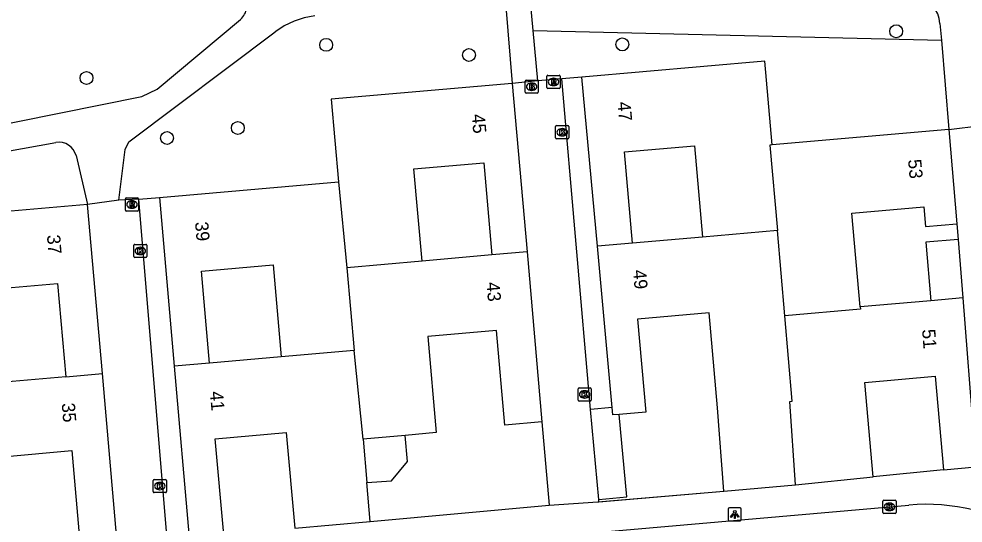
# Model space of a CAD drawing. Extents: x 162990 to 165007, y 383433 to 384336.
# Drawn here: x 164183.1 to 164254.8, y 383936.3 to 383974.6 of the extents above; entities that cross this region are included whole.
import ezdxf

# ---------------------------------------------------------------- set-up
doc = ezdxf.new("R2010")
doc.units = 0
for name, color, linetype in [('IMGEO_Boom', 7, 'Continuous'), ('IMGEO_Brandkraan', 7, 'Continuous'), ('IMGEO_Groenvoorziening', 7, 'Continuous'), ('IMGEO_Kolk', 7, 'Continuous'), ('IMGEO_Lichtpunt', 7, 'Continuous'), ('IMGEO_Muur', 7, 'Continuous'), ('IMGEO_Pand', 7, 'Continuous'), ('IMGEO_Pand_nummerreeks', 7, 'Continuous'), ('IMGEO_Rijbaan_lokaal_open', 7, 'Continuous'), ('IMGEO_Rioolput', 7, 'Continuous'), ('IMGEO_Voetpad_halfverhard', 7, 'Continuous'), ('IMGEO_Voetpad_open', 7, 'Continuous')]:
    doc.layers.add(name, color=color, linetype=linetype)

msp = doc.modelspace()

# ---------------------------------------------------------------- linework, layer by layer
at = {"layer": 'IMGEO_Boom'}
for centre in [(164249.696, 383973.69), (164206.398, 383972.653), (164228.892, 383972.688), (164217.243, 383971.88), (164188.193, 383970.138), (164199.688, 383966.337), (164194.307, 383965.574)]:
    msp.add_circle(centre, 0.489, dxfattribs=at)
at = {"layer": 'IMGEO_Brandkraan'}
for p, q in [((164221.505, 383969.049), (164221.505, 383969.901)), ((164221.58, 383969.975), (164222.432, 383969.975)), ((164221.993, 383969.755), (164222.018, 383969.755)), ((164222.506, 383969.901), (164222.506, 383969.049)), ((164222.432, 383968.975), (164221.58, 383968.975)), ((164222.016, 383969.195), (164221.991, 383969.195))]:
    msp.add_line(p, q, dxfattribs=at)
for points in [[(164221.505, 383969.049), (164221.505, 383969.901)], [(164221.58, 383969.975), (164222.432, 383969.975)], [(164221.853, 383969.675), (164221.853, 383969.275), (164222.066, 383969.275)], [(164222.084, 383969.675), (164221.853, 383969.675)], [(164222.032, 383969.594), (164221.978, 383969.594), (164221.978, 383969.518)], [(164221.978, 383969.518), (164222.031, 383969.518)], [(164222.04, 383969.442), (164221.978, 383969.442), (164221.978, 383969.361)], [(164221.978, 383969.361), (164222.04, 383969.361)], [(164222.506, 383969.901), (164222.506, 383969.049)], [(164222.432, 383968.975), (164221.58, 383968.975)]]:
    msp.add_lwpolyline(points, dxfattribs=at)
for centre, radius, start, end in [((164221.582, 383969.899), 0.0765, 91.55205, 178.44795), ((164221.582, 383969.899), 0.0765, 91.55205, 178.44795), ((164222.033, 383969.556), 0.0379, 267.82845, 90.93552), ((164222.041, 383969.401), 0.0404, 269.87594, 90.50774), ((164222.072, 383969.526), 0.251, 268.66757, 293.53466), ((164222.088, 383969.53), 0.145, 59.4692, 91.53667), ((164222.113, 383969.577), 0.0922, 285.51372, 58.15012), ((164222.118, 383969.385), 0.105, 301.31148, 78.98903), ((164222.43, 383969.899), 0.0765, 1.55205, 88.44795), ((164222.43, 383969.899), 0.0765, 1.55205, 88.44795), ((164221.582, 383969.051), 0.0765, 181.55205, 268.44795), ((164221.582, 383969.051), 0.0765, 181.55205, 268.44795), ((164222.43, 383969.051), 0.0765, 271.55205, 358.44795), ((164222.43, 383969.051), 0.0765, 271.55205, 358.44795)]:
    msp.add_arc(centre, radius, start, end, dxfattribs=at)
for centre, major_axis, ratio, start_param, end_param in [((164221.992, 383969.475), (-0.387, 0.002), 0.722429, 4.712389, 7.853982), ((164222.017, 383969.475), (-0.39, 0.002), 0.717154, 1.570796, 4.712389)]:
    msp.add_ellipse(centre, major_axis=major_axis, ratio=ratio, start_param=start_param, end_param=end_param, dxfattribs=at)
at = {"layer": 'IMGEO_Groenvoorziening'}
for points in [[(164222.131, 383973.745), (164253.129, 383973.007)], [(164225.812, 383970.195), (164224.31, 383970.064)], [(164192.16, 383960.917), (164193.738, 383961.045)]]:
    msp.add_lwpolyline(points, dxfattribs=at)
at = {"layer": 'IMGEO_Kolk'}
for p, q in [((164223.829, 383965.588), (164223.829, 383966.44)), ((164223.904, 383966.514), (164224.756, 383966.514)), ((164224.83, 383966.44), (164224.83, 383965.588)), ((164224.34, 383965.734), (164224.315, 383965.734)), ((164224.317, 383966.294), (164224.342, 383966.294)), ((164224.756, 383965.514), (164223.904, 383965.514)), ((164191.78, 383956.567), (164191.78, 383957.419)), ((164191.855, 383957.493), (164192.707, 383957.493)), ((164192.268, 383957.273), (164192.293, 383957.273)), ((164192.781, 383957.419), (164192.781, 383956.567)), ((164192.707, 383956.493), (164191.855, 383956.493)), ((164192.291, 383956.713), (164192.266, 383956.713)), ((164225.531, 383945.66), (164225.531, 383946.512)), ((164225.606, 383946.586), (164226.458, 383946.586)), ((164226.019, 383946.366), (164226.044, 383946.366)), ((164226.532, 383946.512), (164226.532, 383945.66)), ((164226.042, 383945.806), (164226.017, 383945.806)), ((164226.458, 383945.586), (164225.606, 383945.586)), ((164193.264, 383938.696), (164193.264, 383939.548)), ((164193.339, 383939.622), (164194.191, 383939.622)), ((164193.752, 383939.402), (164193.777, 383939.402)), ((164194.265, 383939.548), (164194.265, 383938.696)), ((164194.191, 383938.622), (164193.339, 383938.622)), ((164193.775, 383938.842), (164193.75, 383938.842)), ((164248.689, 383937.116), (164248.689, 383937.968)), ((164248.764, 383938.042), (164249.616, 383938.042)), ((164249.177, 383937.822), (164249.202, 383937.822)), ((164249.69, 383937.968), (164249.69, 383937.116)), ((164249.616, 383937.042), (164248.764, 383937.042)), ((164249.2, 383937.262), (164249.175, 383937.262))]:
    msp.add_line(p, q, dxfattribs=at)
for points in [[(164223.829, 383965.588), (164223.829, 383966.44)], [(164223.904, 383966.514), (164224.756, 383966.514)], [(164224.83, 383966.44), (164224.83, 383965.588)], [(164224.15, 383966.214), (164224.273, 383966.214), (164224.273, 383966.063), (164224.403, 383966.214), (164224.567, 383966.214), (164224.421, 383966.063), (164224.574, 383965.814), (164224.422, 383965.814), (164224.337, 383965.978), (164224.273, 383965.911), (164224.273, 383965.814), (164224.15, 383965.814), (164224.15, 383966.214)], [(164224.756, 383965.514), (164223.904, 383965.514)], [(164191.78, 383956.567), (164191.78, 383957.419)], [(164191.855, 383957.493), (164192.707, 383957.493)], [(164192.101, 383957.193), (164192.224, 383957.193), (164192.224, 383957.042), (164192.354, 383957.193), (164192.518, 383957.193), (164192.372, 383957.042), (164192.525, 383956.793), (164192.373, 383956.793), (164192.288, 383956.957), (164192.224, 383956.89), (164192.224, 383956.793), (164192.101, 383956.793), (164192.101, 383957.193)], [(164192.781, 383957.419), (164192.781, 383956.567)], [(164192.707, 383956.493), (164191.855, 383956.493)], [(164225.531, 383945.66), (164225.531, 383946.512)], [(164225.606, 383946.586), (164226.458, 383946.586)], [(164226.532, 383946.512), (164226.532, 383945.66)], [(164225.852, 383946.286), (164225.975, 383946.286), (164225.975, 383946.135), (164226.105, 383946.286), (164226.269, 383946.286), (164226.123, 383946.135), (164226.276, 383945.886), (164226.124, 383945.886), (164226.039, 383946.05), (164225.975, 383945.983), (164225.975, 383945.886), (164225.852, 383945.886), (164225.852, 383946.286)], [(164226.458, 383945.586), (164225.606, 383945.586)], [(164193.264, 383938.696), (164193.264, 383939.548)], [(164193.339, 383939.622), (164194.191, 383939.622)], [(164193.585, 383939.322), (164193.708, 383939.322), (164193.708, 383939.171), (164193.838, 383939.322), (164194.002, 383939.322), (164193.856, 383939.171), (164194.009, 383938.922), (164193.857, 383938.922), (164193.772, 383939.086), (164193.708, 383939.019), (164193.708, 383938.922), (164193.585, 383938.922), (164193.585, 383939.322)], [(164194.265, 383939.548), (164194.265, 383938.696)], [(164194.191, 383938.622), (164193.339, 383938.622)], [(164248.689, 383937.116), (164248.689, 383937.968)], [(164248.764, 383938.042), (164249.616, 383938.042)], [(164249.01, 383937.742), (164249.133, 383937.742), (164249.133, 383937.591), (164249.263, 383937.742), (164249.427, 383937.742), (164249.281, 383937.591), (164249.434, 383937.342), (164249.282, 383937.342), (164249.197, 383937.506), (164249.133, 383937.439), (164249.133, 383937.342), (164249.01, 383937.342), (164249.01, 383937.742)], [(164249.69, 383937.968), (164249.69, 383937.116)], [(164249.616, 383937.042), (164248.764, 383937.042)]]:
    msp.add_lwpolyline(points, dxfattribs=at)
for centre, start, end in [((164223.906, 383966.438), 91.55205, 178.44795), ((164223.906, 383966.438), 91.55205, 178.44795), ((164224.754, 383966.438), 1.55205, 88.44795), ((164224.754, 383966.438), 1.55205, 88.44795), ((164223.906, 383965.59), 181.55205, 268.44795), ((164223.906, 383965.59), 181.55205, 268.44795), ((164224.754, 383965.59), 271.55205, 358.44795), ((164224.754, 383965.59), 271.55205, 358.44795), ((164191.857, 383957.417), 91.55205, 178.44795), ((164191.857, 383957.417), 91.55205, 178.44795), ((164192.705, 383957.417), 1.55205, 88.44795), ((164192.705, 383957.417), 1.55205, 88.44795), ((164191.857, 383956.569), 181.55205, 268.44795), ((164191.857, 383956.569), 181.55205, 268.44795), ((164192.705, 383956.569), 271.55205, 358.44795), ((164192.705, 383956.569), 271.55205, 358.44795), ((164225.608, 383946.51), 91.55205, 178.44795), ((164225.608, 383946.51), 91.55205, 178.44795), ((164226.456, 383946.51), 1.55205, 88.44795), ((164226.456, 383946.51), 1.55205, 88.44795), ((164225.608, 383945.662), 181.55205, 268.44795), ((164225.608, 383945.662), 181.55205, 268.44795), ((164226.456, 383945.662), 271.55205, 358.44795), ((164226.456, 383945.662), 271.55205, 358.44795), ((164193.341, 383939.546), 91.55205, 178.44795), ((164193.341, 383939.546), 91.55205, 178.44795), ((164194.189, 383939.546), 1.55205, 88.44795), ((164194.189, 383939.546), 1.55205, 88.44795), ((164193.341, 383938.698), 181.55205, 268.44795), ((164193.341, 383938.698), 181.55205, 268.44795), ((164194.189, 383938.698), 271.55205, 358.44795), ((164194.189, 383938.698), 271.55205, 358.44795), ((164248.766, 383937.966), 91.55205, 178.44795), ((164248.766, 383937.966), 91.55205, 178.44795), ((164249.614, 383937.966), 1.55205, 88.44795), ((164249.614, 383937.966), 1.55205, 88.44795), ((164248.766, 383937.118), 181.55205, 268.44795), ((164248.766, 383937.118), 181.55205, 268.44795), ((164249.614, 383937.118), 271.55205, 358.44795), ((164249.614, 383937.118), 271.55205, 358.44795)]:
    msp.add_arc(centre, 0.0765, start, end, dxfattribs=at)
for centre, major_axis, ratio, start_param, end_param in [((164224.316, 383966.014), (-0.387, 0.002), 0.722429, 4.712389, 7.853982), ((164224.341, 383966.014), (-0.39, 0.002), 0.717154, 1.570796, 4.712389), ((164192.267, 383956.993), (-0.387, 0.002), 0.722429, 4.712389, 7.853982), ((164192.292, 383956.993), (-0.39, 0.002), 0.717154, 1.570796, 4.712389), ((164226.018, 383946.086), (-0.387, 0.002), 0.722429, 4.712389, 7.853982), ((164226.043, 383946.086), (-0.39, 0.002), 0.717154, 1.570796, 4.712389), ((164193.751, 383939.122), (-0.387, 0.002), 0.722429, 4.712389, 7.853982), ((164193.776, 383939.122), (-0.39, 0.002), 0.717154, 1.570796, 4.712389), ((164249.176, 383937.542), (-0.387, 0.002), 0.722429, 4.712389, 7.853982), ((164249.201, 383937.542), (-0.39, 0.002), 0.717154, 1.570796, 4.712389)]:
    msp.add_ellipse(centre, major_axis=major_axis, ratio=ratio, start_param=start_param, end_param=end_param, dxfattribs=at)
at = {"layer": 'IMGEO_Lichtpunt'}
for p, q in [((164236.936, 383937.37), (164236.936, 383936.563)), ((164236.936, 383937.37), (164236.936, 383936.563)), ((164237.838, 383937.465), (164237.03, 383937.465)), ((164237.838, 383937.465), (164237.03, 383937.465)), ((164237.932, 383936.563), (164237.932, 383937.37)), ((164237.932, 383936.563), (164237.932, 383937.37)), ((164237.03, 383936.469), (164237.838, 383936.469)), ((164237.03, 383936.469), (164237.838, 383936.469))]:
    msp.add_line(p, q, dxfattribs=at)
for points in [[(164237.31, 383937.034), (164237.349, 383937.006), (164237.161, 383936.744), (164237.123, 383936.771), (164237.31, 383937.034)], [(164237.522, 383937.006), (164237.56, 383937.033), (164237.747, 383936.771), (164237.708, 383936.743), (164237.522, 383937.006)], [(164237.412, 383936.986), (164237.459, 383936.986), (164237.459, 383936.664), (164237.412, 383936.664), (164237.412, 383936.986)]]:
    msp.add_lwpolyline(points, dxfattribs=at)
msp.add_circle((164237.435, 383937.168), 0.0994, dxfattribs=at)
for centre, start, end in [((164237.03, 383937.37), 90, 180), ((164237.03, 383937.37), 90, 180), ((164237.838, 383937.37), 0, 90), ((164237.838, 383937.37), 0, 90), ((164237.03, 383936.563), 180, 270), ((164237.03, 383936.563), 180, 270), ((164237.838, 383936.563), 270, 0), ((164237.838, 383936.563), 270, 360)]:
    msp.add_arc(centre, 0.0946, start, end, dxfattribs=at)
at = {"layer": 'IMGEO_Muur'}
msp.add_lwpolyline([(164227.04, 383937.919), (164236.601, 383938.736)], dxfattribs=at)
at = {"layer": 'IMGEO_Pand'}
for points in [[(164240.277, 383965.055), (164239.72, 383971.412), (164225.812, 383970.195)], [(164227, 383957.342), (164225.812, 383970.195)], [(164220.535, 383969.72), (164206.787, 383968.516), (164207.337, 383962.235)], [(164220.535, 383969.72), (164221.656, 383956.918)], [(164253.686, 383966.227), (164240.277, 383965.055)], [(164253.686, 383966.227), (164254.313, 383959.063)], [(164240.277, 383965.055), (164240.105, 383965.04), (164240.673, 383958.539)], [(164229.66, 383957.575), (164229.052, 383964.518), (164234.368, 383964.984), (164234.976, 383958.04)], [(164213.681, 383956.221), (164213.068, 383963.229), (164218.376, 383963.693), (164218.989, 383956.685)], [(164193.738, 383961.045), (164207.337, 383962.235)], [(164207.337, 383962.235), (164207.975, 383955.72)], [(164193.738, 383961.045), (164194.86, 383948.235)], [(164188.27, 383960.526), (164174.274, 383959.301)], [(164189.395, 383947.673), (164188.27, 383960.526)], [(164246.958, 383952.731), (164246.334, 383959.859), (164251.805, 383960.338), (164251.935, 383958.855), (164254.313, 383959.063)], [(164240.673, 383958.539), (164234.976, 383958.04)], [(164241.239, 383952.057), (164240.673, 383958.539)], [(164234.976, 383958.04), (164229.66, 383957.575)], [(164254.409, 383957.867), (164251.94, 383957.651), (164252.33, 383953.202)], [(164254.409, 383957.867), (164254.766, 383953.415)], [(164229.66, 383957.575), (164227, 383957.342)], [(164228.132, 383945.102), (164227, 383957.342)], [(164218.989, 383956.685), (164213.681, 383956.221)], [(164221.656, 383956.918), (164218.989, 383956.685)], [(164221.656, 383956.918), (164222.787, 383943.999)], [(164197.541, 383948.47), (164196.929, 383955.453), (164202.36, 383955.929), (164202.971, 383948.945)], [(164213.681, 383956.221), (164207.975, 383955.72)], [(164207.975, 383955.72), (164208.526, 383949.431)], [(164181.354, 383946.969), (164180.733, 383954.066), (164185.992, 383954.526), (164186.614, 383947.43)], [(164252.33, 383953.202), (164246.958, 383952.731)], [(164254.766, 383953.415), (164252.33, 383953.202)], [(164254.766, 383953.415), (164255.591, 383942.692)], [(164236.601, 383938.736), (164236.121, 383945.072), (164235.489, 383952.29), (164230.056, 383951.815), (164230.675, 383944.742), (164228.665, 383944.566)], [(164246.958, 383952.731), (164246.975, 383952.561), (164241.239, 383952.057)], [(164242.041, 383939.221), (164241.621, 383945.554), (164241.805, 383945.571), (164241.239, 383952.057)], [(164222.787, 383943.999), (164219.967, 383943.752), (164219.338, 383950.939), (164214.109, 383950.481), (164214.748, 383943.182), (164212.392, 383942.976)], [(164208.526, 383949.431), (164202.971, 383948.945)], [(164209.196, 383942.696), (164208.526, 383949.431)], [(164202.971, 383948.945), (164197.541, 383948.47)], [(164197.541, 383948.47), (164194.86, 383948.235)], [(164194.86, 383948.235), (164196, 383935.215)], [(164186.614, 383947.43), (164181.354, 383946.969)], [(164186.614, 383947.43), (164189.395, 383947.673)], [(164190.522, 383934.806), (164189.395, 383947.673)], [(164247.936, 383939.823), (164247.308, 383946.999), (164252.667, 383947.468), (164253.29, 383940.358)], [(164228.132, 383945.102), (164226.466, 383944.948)], [(164227.099, 383938.096), (164226.466, 383944.948)], [(164228.665, 383944.566), (164228.185, 383944.524), (164228.132, 383945.102)], [(164227.099, 383938.096), (164229.244, 383938.294), (164228.665, 383944.566)], [(164198.613, 383935.444), (164197.977, 383942.712), (164203.369, 383943.184), (164204.005, 383935.924)], [(164212.392, 383942.976), (164209.196, 383942.696)], [(164209.486, 383939.384), (164211.358, 383939.53), (164212.565, 383940.997), (164212.392, 383942.976)], [(164209.196, 383942.696), (164209.486, 383939.384)], [(164253.29, 383940.358), (164255.754, 383940.574), (164255.591, 383942.692)], [(164182.447, 383934.075), (164181.81, 383941.354), (164187.07, 383941.815), (164187.705, 383934.56)], [(164209.745, 383936.427), (164209.486, 383939.384)], [(164236.601, 383938.736), (164242.041, 383939.221)], [(164242.041, 383939.221), (164247.936, 383939.823)], [(164204.005, 383935.924), (164209.745, 383936.427)]]:
    msp.add_lwpolyline(points, dxfattribs=at)
at = {"layer": 'IMGEO_Rijbaan_lokaal_open'}
msp.add_lwpolyline([(164119.402, 383925.927), (164123.158, 383926.51), (164250.653, 383937.673)], dxfattribs=at)
msp.add_arc((164251.986, 383922.911), 14.822, 20.10116, 95.15892, dxfattribs=at)
at = {"layer": 'IMGEO_Rioolput'}
for p, q in [((164223.169, 383969.412), (164223.169, 383970.264)), ((164223.244, 383970.338), (164224.096, 383970.338)), ((164223.657, 383970.118), (164223.682, 383970.118)), ((164224.17, 383970.264), (164224.17, 383969.412)), ((164224.096, 383969.338), (164223.244, 383969.338)), ((164223.68, 383969.558), (164223.655, 383969.558)), ((164191.144, 383960.094), (164191.144, 383960.946)), ((164191.219, 383961.02), (164192.071, 383961.02)), ((164191.632, 383960.8), (164191.657, 383960.8)), ((164192.145, 383960.946), (164192.145, 383960.094)), ((164192.071, 383960.02), (164191.219, 383960.02)), ((164191.655, 383960.24), (164191.63, 383960.24))]:
    msp.add_line(p, q, dxfattribs=at)
for points in [[(164223.169, 383969.412), (164223.169, 383970.264)], [(164223.244, 383970.338), (164224.096, 383970.338)], [(164223.758, 383970.036), (164223.506, 383970.038), (164223.506, 383969.638)], [(164224.17, 383970.264), (164224.17, 383969.412)], [(164224.096, 383969.338), (164223.244, 383969.338)], [(164223.506, 383969.638), (164223.63, 383969.638), (164223.63, 383969.8), (164223.641, 383969.8)], [(164223.684, 383969.957), (164223.63, 383969.957), (164223.63, 383969.876)], [(164223.63, 383969.876), (164223.682, 383969.876)], [(164223.688, 383969.771), (164223.759, 383969.638), (164223.899, 383969.638), (164223.834, 383969.764)], [(164191.144, 383960.094), (164191.144, 383960.946)], [(164191.219, 383961.02), (164192.071, 383961.02)], [(164191.733, 383960.718), (164191.481, 383960.72), (164191.481, 383960.32)], [(164192.145, 383960.946), (164192.145, 383960.094)], [(164192.071, 383960.02), (164191.219, 383960.02)], [(164191.481, 383960.32), (164191.605, 383960.32), (164191.605, 383960.482), (164191.616, 383960.482)], [(164191.659, 383960.639), (164191.605, 383960.639), (164191.605, 383960.558)], [(164191.605, 383960.558), (164191.657, 383960.558)], [(164191.663, 383960.453), (164191.734, 383960.32), (164191.874, 383960.32), (164191.809, 383960.446)]]:
    msp.add_lwpolyline(points, dxfattribs=at)
for centre, radius, start, end in [((164223.246, 383970.262), 0.0765, 91.55205, 178.44795), ((164223.246, 383970.262), 0.0765, 91.55205, 178.44795), ((164223.757, 383969.926), 0.109, 350.36119, 89.41601), ((164224.094, 383970.262), 0.0765, 1.55205, 88.44795), ((164224.094, 383970.262), 0.0765, 1.55205, 88.44795), ((164223.246, 383969.414), 0.0765, 181.55205, 268.44795), ((164223.246, 383969.414), 0.0765, 181.55205, 268.44795), ((164223.64, 383969.747), 0.0533, 26.02933, 88.69889), ((164223.666, 383970.065), 0.19, 274.7715, 282.96867), ((164223.69, 383969.861), 0.0964, 77.00612, 93.18647), ((164223.704, 383969.918), 0.0378, 276.66336, 79.67722), ((164223.755, 383969.926), 0.112, 277.58423, 350.98172), ((164223.739, 383969.711), 0.108, 29.51342, 73.79051), ((164224.094, 383969.414), 0.0765, 271.55205, 358.44795), ((164224.094, 383969.414), 0.0765, 271.55205, 358.44795), ((164191.221, 383960.944), 0.0765, 91.55205, 178.44795), ((164191.221, 383960.944), 0.0765, 91.55205, 178.44795), ((164191.732, 383960.608), 0.109, 350.36119, 89.41601), ((164192.069, 383960.944), 0.0765, 1.55205, 88.44795), ((164192.069, 383960.944), 0.0765, 1.55205, 88.44795), ((164191.221, 383960.096), 0.0765, 181.55205, 268.44795), ((164191.221, 383960.096), 0.0765, 181.55205, 268.44795), ((164191.615, 383960.429), 0.0533, 26.02933, 88.69889), ((164191.641, 383960.747), 0.19, 274.7715, 282.96867), ((164191.665, 383960.543), 0.0964, 77.00612, 93.18647), ((164191.679, 383960.6), 0.0378, 276.66336, 79.67722), ((164191.73, 383960.608), 0.112, 277.58423, 350.98172), ((164191.714, 383960.393), 0.108, 29.51342, 73.79051), ((164192.069, 383960.096), 0.0765, 271.55205, 358.44795), ((164192.069, 383960.096), 0.0765, 271.55205, 358.44795)]:
    msp.add_arc(centre, radius, start, end, dxfattribs=at)
for centre, major_axis, ratio, start_param, end_param in [((164223.656, 383969.838), (-0.387, 0.002), 0.722429, 4.712389, 7.853982), ((164223.681, 383969.838), (-0.39, 0.002), 0.717154, 1.570796, 4.712389), ((164191.631, 383960.52), (-0.387, 0.002), 0.722429, 4.712389, 7.853982), ((164191.656, 383960.52), (-0.39, 0.002), 0.717154, 1.570796, 4.712389)]:
    msp.add_ellipse(centre, major_axis=major_axis, ratio=ratio, start_param=start_param, end_param=end_param, dxfattribs=at)
at = {"layer": 'IMGEO_Voetpad_halfverhard'}
for points in [[(164222.131, 383973.745), (164221.855, 383976.762)], [(164220.051, 383975.575), (164220.535, 383969.72)], [(164159.337, 383968.037), (164171.84, 383964.982), (164172.749, 383964.863), (164173.662, 383964.945), (164192.407, 383968.721), (164193.559, 383969.275), (164199.894, 383974.594)], [(164190.65, 383960.857), (164191.133, 383964.711), (164191.405, 383965.29), (164202.528, 383973.636)], [(164222.48, 383969.929), (164222.131, 383973.745)], [(164253.024, 383974.29), (164253.129, 383973.007)], [(164253.129, 383973.007), (164253.686, 383966.227)], [(164158.585, 383965.355), (164171.102, 383963.08), (164172.499, 383962.954), (164173.896, 383963.078), (164185.863, 383965.235)], [(164187.399, 383964.235), (164188.27, 383960.526)]]:
    msp.add_lwpolyline(points, dxfattribs=at)
for centre, radius, start, end in [((164250.697, 383974.112), 2.333, 4.38419, 75.81932), ((164199.074, 383975.57), 1.275, 310.04261, 355.04186), ((164206.31, 383968.635), 6.27, 97.02722, 127.09888), ((164186.098, 383963.917), 1.339, 13.73866, 100.12973)]:
    msp.add_arc(centre, radius, start, end, dxfattribs=at)
at = {"layer": 'IMGEO_Voetpad_open'}
for points in [[(164224.31, 383970.064), (164222.48, 383969.929)], [(164226.466, 383944.948), (164224.31, 383970.064)], [(164222.48, 383969.929), (164220.535, 383969.72)], [(164253.686, 383966.227), (164256.154, 383966.522)], [(164190.65, 383960.857), (164188.27, 383960.526)], [(164192.16, 383960.917), (164190.65, 383960.857)], [(164194.329, 383935.05), (164192.16, 383960.917)], [(164254.313, 383959.063), (164254.409, 383957.867)], [(164222.787, 383943.999), (164223.341, 383937.678)], [(164253.29, 383940.358), (164247.936, 383939.823)], [(164227.105, 383937.925), (164236.601, 383938.736)], [(164223.341, 383937.678), (164227.04, 383937.919), (164227.105, 383937.925)], [(164227.105, 383937.925), (164227.099, 383938.096)], [(164209.745, 383936.427), (164223.341, 383937.678)]]:
    msp.add_lwpolyline(points, dxfattribs=at)

# ---------------------------------------------------------------- texts
at = {"layer": 'IMGEO_Pand_nummerreeks'}
for s, rotation, p in [('47', 275.28135, (164228.518, 383968.293)), ('45', 275.00377, (164217.45, 383967.36)), ('53', 275.00184, (164250.596, 383963.924)), ('39', 275.00477, (164196.432, 383959.175)), ('37', 275.00396, (164185.183, 383958.185)), ('49', 275.28246, (164229.698, 383955.523)), ('43', 275.00171, (164218.567, 383954.589)), ('51', 274.40011, (164251.661, 383951.012)), ('41', 275.00171, (164197.56, 383946.29)), ('35', 275.00788, (164186.302, 383945.404))]:
    msp.add_text(s, height=1, rotation=rotation, dxfattribs=at).set_placement(p)

doc.saveas('drawing.dxf')
